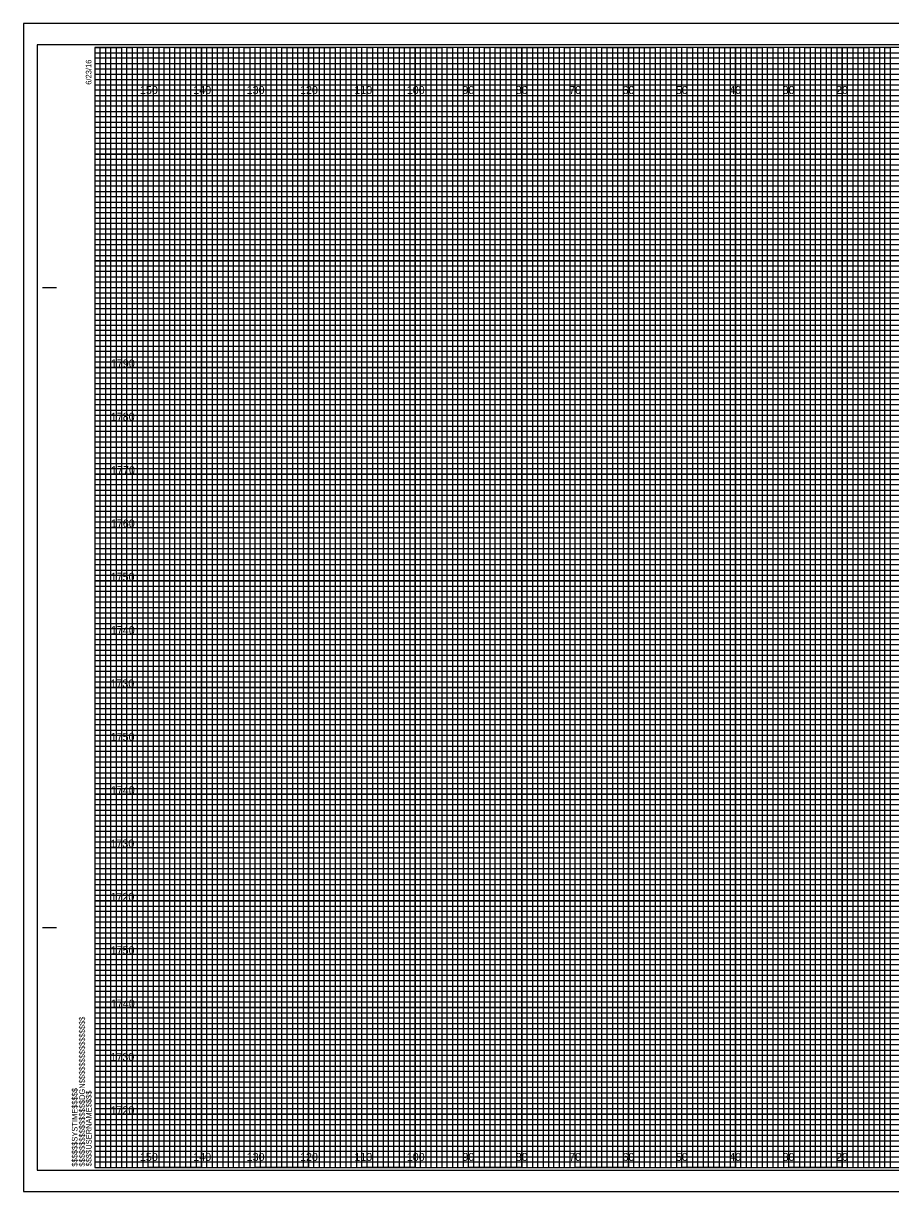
# Model space of a CAD drawing. Extents: x -412 to -75, y -2 to 657.
# Drawn here: x -412.2 to -249.7, y -1.9 to 217.1 of the extents above; entities that cross this region are included whole.
import ezdxf

# ---------------------------------------------------------------- set-up
doc = ezdxf.new("R2010")
doc.units = 0
for name, color, linetype in [('Prop XS Elevation Labels', 7, 'Continuous'), ('Prop XS Offset Labels', 7, 'Continuous'), ('Sheet Cross Section CELL', 7, 'Continuous'), ('Sheet Cross Section Grid Major CELL', 7, 'Continuous'), ('Sheet Cross Section Grid Middle CELL', 7, 'Continuous'), ('Sheet Cross Section Grid Minor 1 CELL', 7, 'Continuous'), ('Sheet Cross Section Grid Minor 2 CELL', 7, 'Continuous'), ('Sheet Cutting Line CELL', 7, 'Continuous'), ('Sheet DOT Grid CELL', 7, 'Continuous'), ('Sheet Plot Border Inside CELL', 7, 'Continuous'), ('Sheet Plot Border Outside CELL', 7, 'Continuous')]:
    doc.layers.add(name, color=color, linetype=linetype)

msp = doc.modelspace()

# ---------------------------------------------------------------- linework, layer by layer
at = {"layer": 'Sheet Cross Section CELL'}
for p, q in [((-408.55, 167.57), (-406.05, 167.57)), ((-408.45, 167.57), (-405.95, 167.57)), ((-408.55, 47.57), (-406.05, 47.57)), ((-408.45, 47.57), (-405.95, 47.57)), ((-398.75, 2.57), (-398.75, 2.57)), ((-398.75, 2.57), (-398.75, 2.57)), ((-398.75, 2.57), (-398.75, 2.57)), ((-398.75, 2.57), (-398.75, 2.57)), ((-398.75, 2.57), (-398.75, 2.57)), ((-398.75, 2.57), (-398.75, 2.57)), ((-398.75, 2.57), (-398.75, 2.57))]:
    msp.add_line(p, q, dxfattribs=at)
msp.add_lwpolyline([(-78.75, 212.57), (-398.75, 212.57), (-398.75, 2.57), (-78.75, 2.57)], close=True, dxfattribs=at)
at = {"layer": 'Sheet Cross Section Grid Major CELL'}
for p, q in [((-388.75, 212.57), (-398.75, 212.57)), ((-388.75, 2.57), (-388.75, 212.57)), ((-368.75, 212.57), (-378.75, 212.57)), ((-378.75, 212.57), (-378.75, 2.57)), ((-368.75, 2.57), (-368.75, 212.57)), ((-348.75, 212.57), (-358.75, 212.57)), ((-358.75, 212.57), (-358.75, 2.57)), ((-348.75, 2.57), (-348.75, 212.57)), ((-328.75, 212.57), (-338.75, 212.57)), ((-338.75, 212.57), (-338.75, 2.57)), ((-328.75, 2.57), (-328.75, 212.57)), ((-308.75, 212.57), (-318.75, 212.57)), ((-318.75, 212.57), (-318.75, 2.57)), ((-308.75, 2.57), (-308.75, 212.57)), ((-288.75, 212.57), (-298.75, 212.57)), ((-298.75, 212.57), (-298.75, 2.57)), ((-288.75, 2.57), (-288.75, 212.57)), ((-268.75, 212.57), (-278.75, 212.57)), ((-278.75, 212.57), (-278.75, 2.57)), ((-268.75, 2.57), (-268.75, 212.57)), ((-248.75, 212.57), (-258.75, 212.57)), ((-258.75, 212.57), (-258.75, 2.57)), ((-378.75, 2.57), (-388.75, 2.57)), ((-358.75, 2.57), (-368.75, 2.57)), ((-338.75, 2.57), (-348.75, 2.57)), ((-318.75, 2.57), (-328.75, 2.57)), ((-298.75, 2.57), (-308.75, 2.57)), ((-278.75, 2.57), (-288.75, 2.57)), ((-258.75, 2.57), (-268.75, 2.57))]:
    msp.add_line(p, q, dxfattribs=at)
for points in [[(-398.75, 202.57), (-78.75, 202.57), (-78.75, 192.57), (-398.75, 192.57)], [(-398.75, 182.57), (-78.75, 182.57), (-78.75, 172.57), (-398.75, 172.57)], [(-398.75, 162.57), (-78.75, 162.57), (-78.75, 152.57), (-398.75, 152.57)], [(-398.75, 142.57), (-78.75, 142.57), (-78.75, 132.57), (-398.75, 132.57)], [(-398.75, 122.57), (-78.75, 122.57), (-78.75, 112.57), (-398.75, 112.57)], [(-398.75, 102.57), (-78.75, 102.57), (-78.75, 92.57), (-398.75, 92.57)], [(-398.75, 82.57), (-78.75, 82.57), (-78.75, 72.57), (-398.75, 72.57)], [(-398.75, 62.57), (-78.75, 62.57), (-78.75, 52.57), (-398.75, 52.57)], [(-398.75, 42.57), (-78.75, 42.57), (-78.75, 32.57), (-398.75, 32.57)], [(-398.75, 22.57), (-78.75, 22.57), (-78.75, 12.57), (-398.75, 12.57)]]:
    msp.add_lwpolyline(points, dxfattribs=at)
at = {"layer": 'Sheet Cross Section Grid Middle CELL'}
for points in [[(-398.75, 212.57), (-393.75, 212.57), (-393.75, 2.57), (-383.75, 2.57), (-383.75, 212.57), (-373.75, 212.57), (-373.75, 2.57), (-363.75, 2.57), (-363.75, 212.57), (-353.75, 212.57), (-353.75, 2.57), (-343.75, 2.57), (-343.75, 212.57), (-333.75, 212.57), (-333.75, 2.57), (-323.75, 2.57), (-323.75, 212.57), (-313.75, 212.57), (-313.75, 2.57), (-303.75, 2.57), (-303.75, 212.57), (-293.75, 212.57), (-293.75, 2.57), (-283.75, 2.57), (-283.75, 212.57), (-273.75, 212.57), (-273.75, 2.57), (-263.75, 2.57), (-263.75, 212.57), (-253.75, 212.57), (-253.75, 2.57), (-243.75, 2.57)], [(-398.75, 207.57), (-123.75, 207.57)], [(-398.75, 187.57), (-78.75, 187.57), (-78.75, 197.57), (-398.75, 197.57)], [(-398.75, 167.57), (-78.75, 167.57), (-78.75, 177.57), (-398.75, 177.57)], [(-398.75, 147.57), (-78.75, 147.57), (-78.75, 157.57), (-398.75, 157.57)], [(-398.75, 127.57), (-78.75, 127.57), (-78.75, 137.57), (-398.75, 137.57)], [(-398.75, 107.57), (-78.75, 107.57), (-78.75, 117.57), (-398.75, 117.57)], [(-398.75, 87.57), (-78.75, 87.57), (-78.75, 97.57), (-398.75, 97.57)], [(-398.75, 67.57), (-78.75, 67.57), (-78.75, 77.57), (-398.75, 77.57)], [(-398.75, 47.57), (-78.75, 47.57), (-78.75, 57.57), (-398.75, 57.57)], [(-398.75, 27.57), (-78.75, 27.57), (-78.75, 37.57), (-398.75, 37.57)], [(-398.75, 7.57), (-78.75, 7.57), (-78.75, 17.57), (-398.75, 17.57)]]:
    msp.add_lwpolyline(points, dxfattribs=at)
at = {"layer": 'Sheet Cross Section Grid Minor 1 CELL'}
for p, q in [((-398.75, 211.57), (-138.75, 211.57)), ((-138.75, 210.55), (-398.75, 210.55)), ((-398.75, 210.55), (-398.75, 209.57)), ((-398.75, 209.57), (-138.75, 209.57)), ((-138.75, 208.46), (-398.75, 208.46)), ((-398.75, 208.46), (-398.75, 206.57)), ((-398.75, 206.57), (-78.75, 206.57))]:
    msp.add_line(p, q, dxfattribs=at)
for points in [[(-398.75, 205.57), (-128.75, 205.57), (-78.75, 205.57), (-78.75, 204.57), (-398.75, 204.57)], [(-398.75, 203.57), (-78.75, 203.57), (-78.75, 201.57), (-398.75, 201.57)], [(-398.75, 200.57), (-78.75, 200.57), (-78.75, 199.57), (-398.75, 199.55)], [(-398.75, 198.57), (-78.75, 198.57), (-78.75, 196.57), (-398.75, 196.57)], [(-398.75, 195.57), (-78.75, 195.57), (-78.75, 194.57), (-398.75, 194.57)], [(-398.75, 193.57), (-78.75, 193.57), (-78.75, 191.57), (-398.75, 191.57)], [(-398.75, 190.57), (-78.75, 190.57), (-78.75, 189.57), (-398.75, 189.57)], [(-398.75, 188.57), (-78.75, 188.57), (-78.75, 186.57), (-398.75, 186.57)], [(-398.75, 185.57), (-78.75, 185.57), (-78.75, 184.57), (-398.75, 184.57)], [(-398.75, 183.57), (-78.75, 183.57), (-78.75, 181.57), (-398.75, 181.57)], [(-398.75, 180.57), (-78.75, 180.57), (-78.75, 179.57), (-398.75, 179.57)], [(-398.75, 178.57), (-78.75, 178.57), (-78.75, 176.52), (-78.75, 175.57), (-78.75, 174.57), (-398.75, 174.57)], [(-398.75, 176.57), (-78.75, 176.57), (-78.75, 175.57), (-398.75, 175.57)], [(-398.75, 173.57), (-78.75, 173.57), (-78.75, 171.57), (-398.75, 171.6)], [(-398.75, 171.6), (-78.75, 171.57), (-78.75, 170.57), (-398.75, 170.57)], [(-398.75, 169.57), (-78.75, 169.57), (-78.75, 168.57), (-398.75, 168.57)], [(-398.75, 166.57), (-78.75, 166.57), (-78.75, 165.57), (-398.75, 165.57)], [(-398.75, 164.57), (-78.75, 164.57), (-78.75, 163.57), (-398.75, 163.57)], [(-398.82, 161.46), (-78.75, 161.46), (-78.75, 160.45), (-398.82, 160.45)], [(-398.75, 159.57), (-78.75, 159.57), (-78.75, 158.57), (-398.75, 158.57)], [(-398.75, 156.57), (-78.75, 156.57), (-78.75, 155.57), (-398.75, 155.57)], [(-398.75, 154.57), (-78.75, 154.57), (-78.75, 153.57), (-398.75, 153.57)], [(-398.75, 151.57), (-78.75, 151.57), (-78.75, 150.57), (-398.75, 150.57)], [(-398.75, 149.57), (-78.75, 149.57), (-78.75, 148.57), (-398.75, 148.57)], [(-398.75, 146.57), (-78.75, 146.57), (-78.75, 145.57), (-398.75, 145.57)], [(-398.75, 144.57), (-78.75, 144.57), (-78.75, 143.57), (-398.75, 143.57)], [(-398.75, 141.57), (-78.75, 141.57), (-78.76, 140.55), (-398.75, 140.57)], [(-398.75, 139.57), (-78.75, 139.57), (-78.75, 138.57), (-398.75, 138.57)], [(-398.75, 136.57), (-78.75, 136.57), (-78.75, 135.57), (-398.75, 135.57)], [(-398.75, 134.57), (-78.75, 134.57), (-78.75, 133.57), (-398.75, 133.57)], [(-398.75, 131.57), (-78.75, 131.57), (-78.75, 130.57), (-398.75, 130.57)], [(-398.75, 129.57), (-78.75, 129.57), (-78.75, 128.57), (-398.75, 128.57)], [(-398.75, 126.57), (-78.75, 126.57), (-78.75, 125.57), (-398.75, 125.57)], [(-398.75, 124.57), (-78.75, 124.57), (-78.75, 123.57), (-398.75, 123.57)], [(-398.75, 121.57), (-78.75, 121.57), (-78.75, 120.57), (-398.75, 120.57)], [(-398.75, 119.56), (-78.68, 119.48), (-78.75, 118.57), (-398.75, 118.57)], [(-398.75, 116.57), (-78.75, 116.57), (-78.75, 115.57), (-398.75, 115.57)], [(-398.75, 114.57), (-78.75, 114.57), (-78.75, 113.57), (-398.75, 113.57)], [(-398.75, 111.57), (-78.75, 111.57), (-78.75, 110.57), (-398.75, 110.57)], [(-398.75, 109.57), (-78.75, 109.57), (-78.75, 108.57), (-398.75, 108.57)], [(-398.75, 106.57), (-78.75, 106.57), (-78.75, 105.57), (-398.75, 105.57)], [(-398.75, 104.57), (-78.75, 104.57), (-78.75, 103.57), (-398.75, 103.57)], [(-398.75, 101.57), (-78.75, 101.57), (-78.75, 100.57), (-398.75, 100.57)], [(-398.75, 99.57), (-78.75, 99.57), (-78.75, 98.57), (-398.75, 98.57)], [(-398.75, 96.57), (-78.75, 96.57), (-78.75, 95.57), (-398.75, 95.57)], [(-398.75, 94.57), (-78.75, 94.57), (-78.75, 93.57), (-398.75, 93.57)], [(-398.75, 91.57), (-78.75, 91.57), (-78.75, 90.57), (-398.75, 90.57)], [(-398.75, 89.57), (-78.75, 89.57), (-78.75, 88.57), (-398.75, 88.57)], [(-398.75, 86.57), (-78.75, 86.57), (-78.75, 85.57), (-398.75, 85.57)], [(-398.75, 84.57), (-78.75, 84.57), (-78.75, 83.57), (-398.75, 83.57)], [(-398.75, 81.57), (-78.75, 81.57), (-78.76, 80.55), (-398.75, 80.57)], [(-398.75, 79.57), (-78.75, 79.57), (-78.75, 78.57), (-398.75, 78.57)], [(-398.75, 76.57), (-78.75, 76.57), (-78.75, 75.57), (-398.75, 75.57)], [(-398.75, 74.57), (-78.75, 74.57), (-78.75, 73.57), (-398.75, 73.57)], [(-398.75, 71.57), (-78.75, 71.57), (-78.75, 70.57), (-398.75, 70.57)], [(-398.75, 69.57), (-78.75, 69.57), (-78.75, 68.57), (-398.75, 68.57)], [(-398.75, 66.57), (-78.75, 66.57), (-78.75, 65.57), (-398.75, 65.57)], [(-398.75, 64.57), (-78.75, 64.57), (-78.75, 63.57), (-398.75, 63.57)], [(-398.75, 61.57), (-78.75, 61.57), (-78.75, 60.57), (-398.75, 60.57)], [(-398.75, 59.56), (-78.68, 59.48), (-78.75, 58.57), (-398.75, 58.57)], [(-398.75, 56.57), (-78.75, 56.57), (-78.75, 55.57), (-398.75, 55.57)], [(-398.75, 54.57), (-78.75, 54.57), (-78.75, 53.57), (-398.75, 53.57)], [(-398.75, 51.57), (-78.75, 51.57), (-78.75, 50.57), (-398.75, 50.57)], [(-398.75, 49.57), (-78.75, 49.57), (-78.75, 48.57), (-398.75, 48.57)], [(-398.75, 46.57), (-78.75, 46.57), (-78.75, 45.57), (-398.75, 45.57)], [(-398.75, 44.57), (-78.75, 44.57), (-78.75, 43.57), (-398.75, 43.57)], [(-398.75, 41.57), (-78.75, 41.57), (-78.75, 40.57), (-398.75, 40.57)], [(-398.75, 39.57), (-78.75, 39.57), (-78.75, 38.57), (-398.75, 38.57)], [(-398.75, 36.57), (-78.75, 36.57), (-78.75, 35.57), (-398.75, 35.57)], [(-398.75, 34.57), (-78.75, 34.57), (-78.75, 33.57), (-398.75, 33.57)], [(-398.75, 31.57), (-78.75, 31.57), (-78.75, 30.57), (-398.75, 30.57)], [(-398.75, 29.57), (-78.75, 29.57), (-78.75, 28.57), (-398.75, 28.57)], [(-398.75, 26.57), (-78.75, 26.57), (-78.75, 25.57), (-398.75, 25.57)], [(-398.75, 24.57), (-78.75, 24.57), (-78.75, 23.57), (-398.75, 23.57)], [(-398.75, 21.57), (-78.75, 21.57), (-78.75, 20.57), (-398.75, 20.57)], [(-398.75, 19.57), (-78.75, 19.57), (-78.75, 18.57), (-398.75, 18.57)], [(-398.75, 16.57), (-78.75, 16.57), (-78.75, 15.57), (-398.75, 15.57)], [(-398.75, 14.57), (-78.75, 14.57), (-78.75, 13.57), (-398.75, 13.57)], [(-398.75, 11.57), (-78.75, 11.57), (-78.75, 10.57), (-398.75, 10.57)], [(-398.75, 9.57), (-78.75, 9.57), (-78.75, 8.57), (-398.75, 8.57)], [(-398.75, 6.57), (-78.75, 6.57), (-78.75, 5.57), (-398.75, 5.57)], [(-398.75, 4.57), (-78.75, 4.57), (-78.75, 3.57), (-398.75, 3.57)]]:
    msp.add_lwpolyline(points, dxfattribs=at)
at = {"layer": 'Sheet Cross Section Grid Minor 2 CELL'}
for points in [[(-398.75, 2.57), (-397.75, 2.57), (-397.75, 212.57), (-396.75, 212.57), (-396.75, 2.57)], [(-396.75, 2.57), (-395.75, 2.57), (-395.75, 212.57), (-394.75, 212.57), (-394.75, 2.57)], [(-393.75, 2.57), (-392.75, 2.57), (-392.75, 212.57), (-391.75, 212.57), (-391.75, 2.57)], [(-391.75, 2.57), (-390.75, 2.57), (-390.75, 212.57), (-389.75, 212.57), (-389.75, 2.57)], [(-388.75, 2.57), (-387.75, 2.57), (-387.75, 212.57), (-386.75, 212.57), (-386.75, 2.57)], [(-386.75, 2.57), (-385.75, 2.57), (-385.75, 212.57), (-384.75, 212.57), (-384.75, 2.57)], [(-383.75, 2.57), (-382.75, 2.57), (-382.75, 212.57), (-381.75, 212.57), (-381.75, 2.57)], [(-381.75, 2.57), (-380.75, 2.57), (-380.75, 212.57), (-379.75, 212.57), (-379.75, 2.57)], [(-378.75, 2.57), (-377.75, 2.57), (-377.75, 212.57), (-376.75, 212.57), (-376.75, 2.57)], [(-376.75, 2.57), (-375.75, 2.57), (-375.75, 212.57), (-374.75, 212.57), (-374.75, 2.57)], [(-373.75, 2.57), (-372.75, 2.57), (-372.75, 212.57), (-371.75, 212.57), (-371.75, 2.57)], [(-371.75, 2.57), (-370.75, 2.57), (-370.75, 212.57), (-369.75, 212.57), (-369.75, 2.57)], [(-368.75, 2.57), (-367.75, 2.57), (-367.75, 212.57), (-366.75, 212.57), (-366.75, 2.57)], [(-366.75, 2.57), (-365.75, 2.57), (-365.75, 212.57), (-364.75, 212.57), (-364.75, 2.57)], [(-363.75, 2.57), (-362.75, 2.57), (-362.75, 212.57), (-361.75, 212.57), (-361.75, 2.57)], [(-361.75, 2.57), (-360.75, 2.57), (-360.75, 212.57), (-359.75, 212.57), (-359.75, 2.57)], [(-358.75, 2.57), (-357.75, 2.57), (-357.75, 212.57), (-356.75, 212.57), (-356.75, 2.57)], [(-356.75, 2.57), (-355.75, 2.57), (-355.75, 212.57), (-354.75, 212.57), (-354.75, 2.57)], [(-353.75, 2.57), (-352.75, 2.57), (-352.75, 212.57), (-351.75, 212.57), (-351.75, 2.57)], [(-351.75, 2.57), (-350.75, 2.57), (-350.75, 212.57), (-349.75, 212.57), (-349.75, 2.57)], [(-348.75, 2.57), (-347.75, 2.57), (-347.75, 212.57), (-346.75, 212.57), (-346.75, 2.57)], [(-346.75, 2.57), (-345.75, 2.57), (-345.75, 212.57), (-344.75, 212.57), (-344.75, 2.57)], [(-343.75, 2.57), (-342.75, 2.57), (-342.75, 212.57), (-341.75, 212.57), (-341.75, 2.57)], [(-341.75, 2.57), (-340.75, 2.57), (-340.75, 212.57), (-339.75, 212.57), (-339.75, 2.57)], [(-338.75, 2.57), (-337.75, 2.57), (-337.75, 212.57), (-336.75, 212.57), (-336.75, 2.57)], [(-336.75, 2.57), (-335.75, 2.57), (-335.75, 212.57), (-334.75, 212.57), (-334.75, 2.57)], [(-333.75, 2.57), (-332.75, 2.57), (-332.75, 212.57), (-331.75, 212.57), (-331.75, 2.57)], [(-331.75, 2.57), (-330.75, 2.57), (-330.75, 212.57), (-329.75, 212.57), (-329.75, 2.57)], [(-328.75, 2.57), (-327.75, 2.57), (-327.75, 212.57), (-326.75, 212.57), (-326.75, 2.57)], [(-326.75, 2.57), (-325.75, 2.57), (-325.75, 212.57), (-324.75, 212.57), (-324.75, 2.57)], [(-323.75, 2.57), (-322.75, 2.57), (-322.75, 212.57), (-321.75, 212.57), (-321.75, 2.57)], [(-321.75, 2.57), (-320.75, 2.57), (-320.75, 212.57), (-319.75, 212.57), (-319.75, 2.57)], [(-318.75, 2.57), (-317.75, 2.57), (-317.75, 212.57), (-316.75, 212.57), (-316.75, 2.57)], [(-316.75, 2.57), (-315.75, 2.57), (-315.75, 212.57), (-314.75, 212.57), (-314.75, 2.57)], [(-313.75, 2.57), (-312.75, 2.57), (-312.75, 212.57), (-311.75, 212.57), (-311.75, 2.57)], [(-311.75, 2.57), (-310.75, 2.57), (-310.75, 212.57), (-309.75, 212.57), (-309.75, 2.57)], [(-308.75, 2.57), (-307.75, 2.57), (-307.75, 212.57), (-306.75, 212.57), (-306.75, 2.57)], [(-306.75, 2.57), (-305.75, 2.57), (-305.75, 212.57), (-304.75, 212.57), (-304.75, 2.57)], [(-303.75, 2.57), (-302.75, 2.57), (-302.75, 212.57), (-301.75, 212.57), (-301.75, 2.57)], [(-301.75, 2.57), (-300.75, 2.57), (-300.75, 212.57), (-299.75, 212.57), (-299.75, 2.57)], [(-298.75, 2.57), (-297.75, 2.57), (-297.75, 212.57), (-296.75, 212.57), (-296.75, 2.57)], [(-296.75, 2.57), (-295.75, 2.57), (-295.75, 212.57), (-294.75, 212.57), (-294.75, 2.57)], [(-293.75, 2.57), (-292.75, 2.57), (-292.75, 212.57), (-291.75, 212.57), (-291.75, 2.57)], [(-291.75, 2.57), (-290.75, 2.57), (-290.75, 212.57), (-289.75, 212.57), (-289.75, 2.57)], [(-288.75, 2.57), (-287.75, 2.57), (-287.75, 212.57), (-286.75, 212.57), (-286.75, 2.57)], [(-286.75, 2.57), (-285.75, 2.57), (-285.75, 212.57), (-284.75, 212.57), (-284.75, 2.57)], [(-283.75, 2.57), (-282.75, 2.57), (-282.75, 212.57), (-281.75, 212.57), (-281.75, 2.57)], [(-281.75, 2.57), (-280.75, 2.57), (-280.75, 212.57), (-279.75, 212.57), (-279.75, 2.57)], [(-278.75, 2.57), (-277.75, 2.57), (-277.75, 212.57), (-276.75, 212.57), (-276.75, 2.57)], [(-276.75, 2.57), (-275.75, 2.57), (-275.75, 212.57), (-274.75, 212.57), (-274.75, 2.57)], [(-273.75, 2.57), (-272.75, 2.57), (-272.75, 212.57), (-271.75, 212.57), (-271.75, 2.57)], [(-271.75, 2.57), (-270.75, 2.57), (-270.75, 212.57), (-269.75, 212.57), (-269.75, 2.57)], [(-268.75, 2.57), (-267.75, 2.57), (-267.75, 212.57), (-266.75, 212.57), (-266.75, 2.57)], [(-266.75, 2.57), (-265.75, 2.57), (-265.75, 212.57), (-264.75, 212.57), (-264.75, 2.57)], [(-263.75, 2.57), (-262.75, 2.57), (-262.75, 212.57), (-261.75, 212.57), (-261.75, 2.57)], [(-261.75, 2.57), (-260.75, 2.57), (-260.75, 212.57), (-259.75, 212.57), (-259.75, 2.57)], [(-258.75, 2.57), (-257.75, 2.57), (-257.75, 212.57), (-256.75, 212.57), (-256.75, 2.57)], [(-256.75, 2.57), (-255.75, 2.57), (-255.75, 212.57), (-254.75, 212.57), (-254.75, 2.57)], [(-253.75, 2.57), (-252.75, 2.57), (-252.75, 212.57), (-251.75, 212.57), (-251.75, 2.57)], [(-251.75, 2.57), (-250.75, 2.57), (-250.75, 212.57), (-249.75, 212.57), (-249.75, 2.57)]]:
    msp.add_lwpolyline(points, dxfattribs=at)
at = {"layer": 'Sheet Cutting Line CELL'}
for p, q in [((-75.45, 217.07), (-412.15, 217.07)), ((-412.15, 217.07), (-412.15, -1.93)), ((-412.15, -1.93), (-75.45, -1.93))]:
    msp.add_line(p, q, dxfattribs=at)
at = {"layer": 'Sheet DOT Grid CELL'}
for p, q in [((-388.75, 2.57), (-388.75, 212.57)), ((-378.75, 2.57), (-378.75, 212.57)), ((-368.75, 2.57), (-368.75, 212.57)), ((-358.75, 2.57), (-358.75, 212.57)), ((-348.75, 2.57), (-348.75, 212.57)), ((-338.75, 2.57), (-338.75, 212.57)), ((-328.75, 2.57), (-328.75, 212.57)), ((-318.75, 2.57), (-318.75, 212.57)), ((-308.75, 2.57), (-308.75, 212.57)), ((-298.75, 2.57), (-298.75, 212.57)), ((-288.75, 2.57), (-288.75, 212.57)), ((-278.75, 2.57), (-278.75, 212.57)), ((-268.75, 2.57), (-268.75, 212.57)), ((-258.75, 2.57), (-258.75, 212.57)), ((-398.75, 202.57), (-78.75, 202.57)), ((-398.75, 192.57), (-78.75, 192.57)), ((-398.75, 182.57), (-78.75, 182.57)), ((-398.75, 172.57), (-78.75, 172.57)), ((-398.75, 162.57), (-78.75, 162.57)), ((-398.75, 152.57), (-78.75, 152.57)), ((-398.75, 142.57), (-78.75, 142.57)), ((-398.75, 132.57), (-78.75, 132.57)), ((-398.75, 122.57), (-78.75, 122.57)), ((-398.75, 112.57), (-78.75, 112.57)), ((-398.75, 102.57), (-78.75, 102.57)), ((-398.75, 92.57), (-78.75, 92.57)), ((-398.75, 82.57), (-78.75, 82.57)), ((-398.75, 72.57), (-78.75, 72.57)), ((-398.75, 62.57), (-78.75, 62.57)), ((-398.75, 52.57), (-78.75, 52.57)), ((-398.75, 42.57), (-78.75, 42.57)), ((-398.75, 32.57), (-78.75, 32.57)), ((-398.75, 22.57), (-78.75, 22.57)), ((-398.75, 12.57), (-78.75, 12.57))]:
    msp.add_line(p, q, dxfattribs=at)
at = {"layer": 'Sheet Plot Border Inside CELL'}
msp.add_lwpolyline([(-409.55, 2.07), (-76.35, 2.07), (-76.35, 213.07), (-409.55, 213.07)], close=True, dxfattribs=at)
at = {"layer": 'Sheet Plot Border Outside CELL'}
msp.add_lwpolyline([(-412.15, -1.93), (-75.45, -1.93), (-75.45, 217.07), (-412.15, 217.07)], close=True, dxfattribs=at)

# ---------------------------------------------------------------- texts
at = {"layer": 'Prop XS Elevation Labels'}
for s, p in [('1790', (-395.75, 152.57)), ('1780', (-395.77, 142.57)), ('1770', (-395.71, 132.57)), ('1760', (-395.75, 122.57)), ('1750', (-395.79, 112.57)), ('1740', (-395.75, 102.57)), ('1730', (-395.83, 92.57)), ('1750', (-395.79, 82.57)), ('1740', (-395.75, 72.57)), ('1730', (-395.83, 62.57)), ('1720', (-395.82, 52.57)), ('1750', (-395.79, 42.57)), ('1740', (-395.75, 32.57)), ('1730', (-395.83, 22.57)), ('1720', (-395.82, 12.57))]:
    msp.add_text(s, height=1.5, dxfattribs=at).set_placement(p)
at = {"layer": 'Prop XS Offset Labels'}
for s, p in [('150', (-390.31, 203.82)), ('140', (-380.31, 203.82)), ('130', (-370.31, 203.82)), ('120', (-360.31, 203.82)), ('110', (-350.13, 203.82)), ('100', (-340.31, 203.82)), ('90', (-329.89, 203.82)), ('80', (-319.89, 203.82)), ('70', (-309.89, 203.82)), ('60', (-299.89, 203.82)), ('50', (-289.89, 203.82)), ('40', (-279.89, 203.82)), ('30', (-269.89, 203.82)), ('20', (-259.89, 203.82)), ('150', (-390.31, 3.82)), ('140', (-380.31, 3.82)), ('130', (-370.31, 3.82)), ('120', (-360.31, 3.82)), ('110', (-350.13, 3.82)), ('100', (-340.31, 3.82)), ('90', (-329.89, 3.82)), ('80', (-319.89, 3.82)), ('70', (-309.89, 3.82)), ('60', (-299.89, 3.82)), ('50', (-289.89, 3.82)), ('40', (-279.89, 3.82)), ('30', (-269.89, 3.82)), ('20', (-259.89, 3.82))]:
    msp.add_text(s, height=1.5, dxfattribs=at).set_placement(p)
at = {"layer": 'Sheet Cross Section CELL'}
for s, p in [('6/23/16', (-399.4, 205.57)), ('$$$$$$$$$$$$$$$$DGN$$$$$$$$$$$$$$$$', (-400.63, 2.75)), ('$$$$$$SYSTIME$$$$$', (-402.01, 2.75)), ('$$$$USERNAME$$$$', (-399.37, 2.8))]:
    msp.add_text(s, height=1.05, rotation=90, dxfattribs=at).set_placement(p)

doc.saveas('drawing.dxf')
